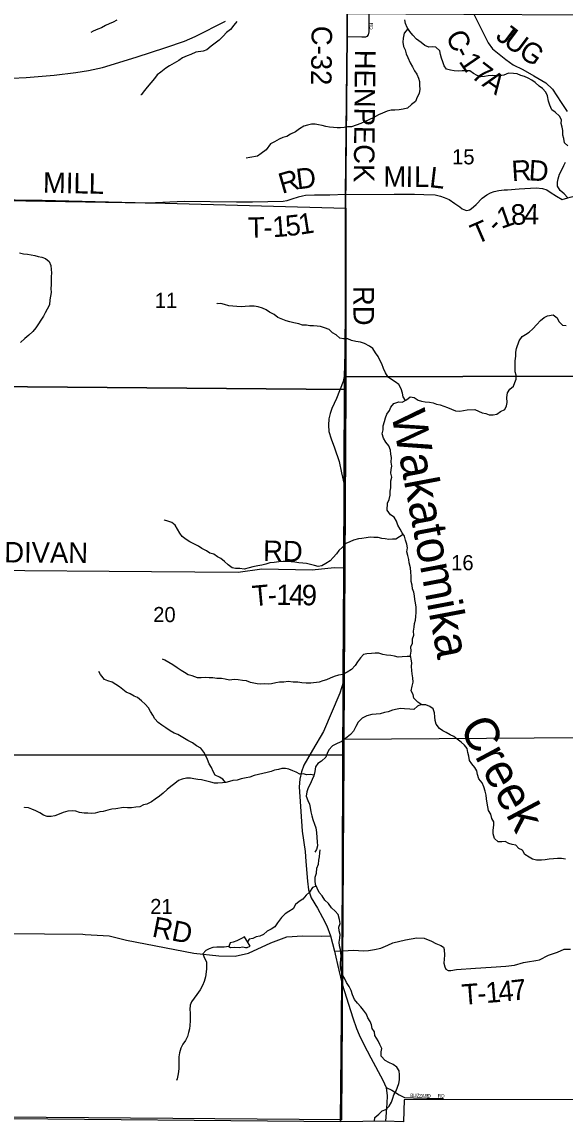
# Model space of a CAD drawing. Extents: x 1759416 to 2214760, y 252598 to 1116833.
# Drawn here: x 2024050 to 2031996, y 815661 to 831751 of the extents above; entities that cross this region are included whole.
import ezdxf

# ---------------------------------------------------------------- set-up
doc = ezdxf.new("R2010")
doc.units = 0
for name, color, linetype in [('GM_X_Adjacent_County', 7, 'Continuous'), ('GM_X_County', 7, 'Continuous'), ('GM_X_County_Road', 7, 'Continuous'), ('GM_X_County_Road_Text', 7, 'Continuous'), ('GM_X_Minor_Lake', 7, 'Continuous'), ('GM_X_Minor_River', 7, 'Continuous'), ('GM_X_Minor_River_Text', 7, 'Continuous'), ('GM_X_Section', 7, 'Continuous'), ('GM_X_Section_Text', 7, 'Continuous'), ('GM_X_State_Route', 7, 'Continuous'), ('GM_X_Township', 7, 'Continuous'), ('GM_X_Township_Road', 7, 'Continuous'), ('GM_X_Township_Road_Text', 7, 'Continuous'), ('GM_X_Township_ROW', 7, 'Continuous'), ('GM_X_Township_Subdivision', 7, 'Continuous'), ('GM_X_Township_Subdivision_Text', 7, 'Continuous')]:
    doc.layers.add(name, color=color, linetype=linetype)

msp = doc.modelspace()

# ---------------------------------------------------------------- linework, layer by layer
at = {"layer": 'GM_X_Adjacent_County'}
msp.add_lwpolyline([(2032253, 815990), (2029643, 815984), (2029631, 815665), (2029362, 815671), (2028709, 815661), (2023356, 815714), (2021728, 815742), (2020383, 815765), (2017999, 815806), (2014117, 815901), (2012614, 815938), (2008904, 816114), (2007002, 816215), (2006296, 816251), (2001880, 816522), (2001221, 816534)], dxfattribs=at)
at = {"layer": 'GM_X_County'}
msp.add_lwpolyline([(2032253, 815990), (2029643, 815984), (2029631, 815665), (2029362, 815671), (2028709, 815661), (2023356, 815714), (2021728, 815742), (2020383, 815765), (2017999, 815806), (2014117, 815901), (2012614, 815938), (2008904, 816114), (2007002, 816215), (2006296, 816251), (2001880, 816522), (2001221, 816534)], dxfattribs=at)
at = {"layer": 'GM_X_County_Road'}
for points in [[(2028809, 831909), (2028807, 831533), (2028785, 829229), (2028783, 827584), (2028777, 826935), (2028774, 826712), (2028769, 826590), (2028751, 826495), (2028652, 826246), (2028583, 826099), (2028560, 826027), (2028542, 825946), (2028534, 825855), (2028542, 825763), (2028573, 825656), (2028624, 825522), (2028690, 825322), (2028724, 825155), (2028763, 824988), (2028758, 823761), (2028754, 822861), (2028752, 822299), (2028751, 822090), (2028703, 821935), (2028461, 821373), (2028303, 821102), (2028172, 820880), (2028142, 820782), (2028115, 820674), (2028108, 820562), (2028149, 819914), (2028194, 819620), (2028203, 819471), (2028227, 819183), (2028245, 819057), (2028283, 818942), (2028373, 818791), (2028446, 818651), (2028509, 818532), (2028563, 818382)], [(2030657, 831875), (2030872, 831447), (2030934, 831359), (2031130, 831202), (2031239, 831126), (2031378, 831057), (2031540, 830965), (2031717, 830859), (2031813, 830767), (2031940, 830576), (2032029, 830443)], [(2028563, 818382), (2028622, 818160), (2028644, 818070), (2028665, 817965), (2028729, 817695), (2028735, 817678)], [(2028735, 817678), (2028893, 817184), (2028944, 817028), (2028983, 816934), (2029046, 816805), (2029153, 816600), (2029329, 816275), (2029379, 816168), (2029395, 816045), (2029390, 815938), (2029381, 815802), (2029369, 815671)]]:
    msp.add_lwpolyline(points, dxfattribs=at)
at = {"layer": 'GM_X_Minor_Lake'}
for points in [[(2027306, 818369), (2027262, 818345), (2027196, 818311), (2027138, 818293), (2027096, 818284), (2027076, 818228), (2027100, 818212), (2027162, 818217), (2027228, 818215), (2027280, 818221), (2027322, 818215), (2027346, 818213), (2027390, 818231)], [(2027306, 818369), (2027262, 818345), (2027196, 818311), (2027138, 818293), (2027096, 818284), (2027076, 818228), (2027100, 818212), (2027162, 818217), (2027228, 818215), (2027280, 818221), (2027322, 818215), (2027346, 818213), (2027390, 818231)], [(2027390, 818231), (2027306, 818369)]]:
    msp.add_lwpolyline(points, dxfattribs=at)
at = {"layer": 'GM_X_Minor_River'}
for points in [[(2025436, 831777), (2025384, 831747), (2025324, 831725), (2025270, 831701), (2025214, 831668), (2025158, 831646), (2025092, 831616), (2025058, 831600)], [(2027195, 831758), (2027151, 831704), (2027103, 831642), (2027045, 831598), (2026995, 831544), (2026933, 831485), (2026879, 831441), (2026817, 831399), (2026755, 831345), (2026703, 831325), (2026595, 831309), (2026523, 831275), (2026467, 831256), (2026399, 831228), (2026347, 831190), (2026207, 831110), (2026153, 831074), (2026081, 831017), (2026030, 830977), (2025988, 830923), (2025884, 830799), (2025844, 830747), (2025796, 830686), (2025788, 830684)], [(2030176, 831276), (2030164, 831328), (2030105, 831382), (2030053, 831388), (2030001, 831384), (2029943, 831406), (2029891, 831452), (2029821, 831500), (2029769, 831558), (2029723, 831612), (2029685, 831670), (2029661, 831728), (2029651, 831783)], [(2029698, 831650), (2029643, 831590), (2029629, 831516), (2029621, 831456), (2029635, 831394), (2029655, 831343), (2029673, 831287), (2029697, 831233), (2029728, 831153), (2029762, 831095), (2029792, 831039), (2029826, 830989), (2029852, 830932), (2029866, 830880), (2029868, 830820), (2029872, 830768), (2029862, 830706), (2029834, 830652), (2029806, 830590), (2029752, 830545), (2029693, 830491), (2029628, 830475), (2029570, 830467), (2029504, 830461), (2029450, 830463), (2029392, 830445), (2029324, 830417), (2029266, 830392), (2029200, 830356), (2029126, 830322), (2029074, 830294), (2029008, 830268), (2028938, 830240), (2028872, 830220), (2028814, 830216), (2028764, 830210), (2028712, 830204), (2028660, 830201), (2028610, 830209), (2028552, 830215), (2028498, 830225), (2028442, 830239), (2028390, 830247), (2028340, 830257), (2028286, 830255), (2028230, 830243), (2028174, 830227), (2028112, 830187), (2028052, 830147), (2027978, 830111), (2027924, 830076), (2027866, 830060), (2027812, 830036), (2027746, 829998), (2027688, 829970), (2027622, 829882), (2027552, 829827), (2027496, 829791), (2027386, 829769), (2027332, 829759)], [(2032039, 829938), (2031989, 829984), (2031977, 830048), (2031965, 830098), (2031962, 830162), (2031956, 830214), (2031942, 830267), (2031944, 830319), (2031914, 830375), (2031854, 830431), (2031802, 830467), (2031772, 830535), (2031754, 830591), (2031738, 830669), (2031715, 830726), (2031669, 830778), (2031619, 830814), (2031561, 830866), (2031511, 830902), (2031455, 830928), (2031403, 830956), (2031351, 830970), (2031297, 830994), (2031243, 830998), (2031167, 831004), (2031103, 830974), (2031049, 830966), (2030985, 830966), (2030931, 830970), (2030873, 830963), (2030819, 830953), (2030763, 830949), (2030710, 830967), (2030658, 830999), (2030602, 831035), (2030544, 831039), (2030492, 831035), (2030434, 831031), (2030374, 831037), (2030320, 831045), (2030264, 831059), (2030230, 831111), (2030210, 831169), (2030190, 831224), (2030176, 831276)], [(2032032, 829182), (2031982, 829238), (2031926, 829286), (2031888, 829350), (2031888, 829408), (2031897, 829458), (2031917, 829524), (2031951, 829589), (2031977, 829651), (2032001, 829701)], [(2024014, 828377), (2024070, 828361), (2024132, 828353), (2024236, 828337), (2024288, 828323), (2024341, 828313), (2024393, 828291), (2024447, 828247), (2024471, 828188), (2024477, 828132), (2024481, 828080), (2024479, 828022), (2024475, 827960), (2024477, 827908), (2024473, 827852), (2024475, 827795), (2024469, 827739), (2024458, 827685), (2024452, 827615), (2024420, 827553), (2024390, 827498), (2024364, 827448), (2024326, 827392), (2024290, 827336), (2024254, 827278), (2024210, 827226), (2024152, 827169), (2024094, 827123), (2024026, 827065)], [(2029661, 826216), (2029629, 826270), (2029617, 826320), (2029597, 826384), (2029565, 826450), (2029510, 826488), (2029456, 826522), (2029406, 826558), (2029368, 826620), (2029338, 826685), (2029314, 826749), (2029288, 826805), (2029260, 826857), (2029224, 826913), (2029185, 826973), (2029133, 827009), (2029063, 827049), (2029005, 827067), (2028937, 827079), (2028873, 827093), (2028817, 827115), (2028755, 827119), (2028703, 827125), (2028645, 827173), (2028593, 827205), (2028543, 827251), (2028479, 827277), (2028420, 827295), (2028370, 827303), (2028316, 827309), (2028264, 827309), (2028212, 827317), (2028156, 827319), (2028100, 827335), (2028026, 827349), (2027970, 827363), (2027918, 827379), (2027844, 827409), (2027792, 827431), (2027738, 827471), (2027674, 827509), (2027624, 827539), (2027568, 827565), (2027507, 827587), (2027447, 827593), (2027381, 827595), (2027317, 827589), (2027259, 827583), (2027195, 827589), (2027133, 827593), (2027075, 827601), (2027013, 827617), (2026959, 827635), (2026909, 827631), (2026907, 827637)], [(2029437, 824828), (2029439, 824888), (2029445, 824938), (2029445, 825042), (2029461, 825094), (2029446, 825151), (2029450, 825203), (2029462, 825255), (2029450, 825313), (2029456, 825379), (2029448, 825431), (2029444, 825487), (2029420, 825554), (2029372, 825604), (2029342, 825662), (2029321, 825728), (2029335, 825784), (2029337, 825842), (2029353, 825908), (2029369, 825961), (2029387, 826013), (2029427, 826069), (2029449, 826119), (2029493, 826169), (2029563, 826195), (2029615, 826191), (2029675, 826224), (2029731, 826266), (2029789, 826260), (2029845, 826220), (2029897, 826206), (2029951, 826194), (2030011, 826188), (2030065, 826180), (2030115, 826162), (2030167, 826150), (2030221, 826130), (2030275, 826112), (2030336, 826088), (2030396, 826066), (2030456, 826058), (2030512, 826068), (2030562, 826078), (2030678, 826082), (2030728, 826058), (2030786, 826036), (2030836, 826024), (2030886, 826004), (2030944, 826004), (2030996, 826016), (2031052, 826054), (2031116, 826083), (2031142, 826135), (2031152, 826187), (2031144, 826261), (2031154, 826327), (2031190, 826379), (2031242, 826426), (2031260, 826476), (2031282, 826526), (2031279, 826586), (2031267, 826636), (2031269, 826694), (2031267, 826744), (2031265, 826795), (2031275, 826863), (2031277, 826921), (2031287, 826975), (2031325, 827089), (2031367, 827152), (2031419, 827180), (2031471, 827216), (2031527, 827264), (2031585, 827328), (2031636, 827384), (2031690, 827431), (2031742, 827451), (2031824, 827469), (2031881, 827425), (2031907, 827371), (2031957, 827315), (2032011, 827313)], [(2031372, 819637), (2031318, 819661), (2031274, 819712), (2031224, 819718), (2031174, 819734), (2031122, 819762), (2031070, 819757), (2031018, 819761), (2030962, 819810), (2030943, 819878), (2030947, 819928), (2030953, 820002), (2030955, 820052), (2030927, 820102), (2030909, 820162), (2030877, 820215), (2030867, 820273), (2030857, 820323), (2030845, 820389), (2030840, 820441), (2030830, 820501), (2030810, 820563), (2030784, 820620), (2030736, 820682), (2030714, 820746), (2030706, 820798), (2030676, 820848), (2030632, 820900), (2030598, 820950), (2030589, 821012), (2030573, 821065), (2030563, 821123), (2030525, 821175), (2030475, 821217), (2030419, 821263), (2030369, 821301), (2030317, 821323), (2030259, 821357), (2030209, 821381), (2030159, 821415), (2030112, 821481), (2030094, 821533), (2030092, 821588), (2030086, 821648), (2030066, 821706), (2030016, 821740), (2029958, 821762), (2029902, 821762), (2029844, 821804), (2029786, 821862), (2029772, 821916), (2029745, 821970), (2029759, 822034), (2029773, 822095), (2029771, 822159), (2029761, 822217), (2029755, 822267), (2029749, 822325), (2029753, 822377), (2029747, 822429), (2029737, 822488), (2029745, 822548), (2029740, 822610), (2029762, 822666), (2029764, 822728), (2029782, 822784), (2029780, 822839), (2029788, 822901), (2029796, 822951), (2029808, 823001), (2029812, 823055), (2029820, 823113), (2029816, 823192), (2029808, 823254), (2029799, 823304), (2029795, 823356), (2029785, 823410), (2029765, 823460), (2029759, 823514), (2029745, 823567), (2029743, 823645), (2029741, 823705), (2029733, 823765), (2029717, 823839), (2029710, 823891), (2029696, 823948), (2029682, 824000), (2029692, 824062), (2029680, 824114), (2029664, 824170), (2029646, 824228), (2029612, 824280), (2029586, 824334), (2029552, 824391), (2029530, 824451), (2029495, 824509), (2029443, 824543), (2029395, 824609), (2029399, 824711), (2029423, 824767), (2029437, 824828)], [(2029627, 824256), (2029572, 824220), (2029520, 824184), (2029470, 824186), (2029416, 824180), (2029366, 824190), (2029314, 824196), (2029264, 824210), (2029200, 824212), (2029146, 824216), (2029088, 824208), (2029022, 824198), (2028972, 824189), (2028900, 824171), (2028848, 824149), (2028790, 824121), (2028740, 824069), (2028688, 824023), (2028654, 823971), (2028602, 823920), (2028558, 823868), (2028494, 823828), (2028440, 823794), (2028386, 823788), (2028328, 823802), (2028274, 823818), (2028212, 823828), (2028160, 823836), (2028102, 823842), (2028045, 823850), (2027991, 823856), (2027931, 823862), (2027871, 823862), (2027809, 823856), (2027739, 823847), (2027679, 823839), (2027617, 823821), (2027559, 823805), (2027499, 823795), (2027427, 823781), (2027373, 823769), (2027299, 823749), (2027239, 823759), (2027175, 823757), (2027125, 823767), (2027067, 823813), (2027013, 823861), (2026959, 823905), (2026909, 823927), (2026857, 823965), (2026800, 823983), (2026748, 824017), (2026684, 824051), (2026634, 824083), (2026564, 824117), (2026504, 824147), (2026454, 824183), (2026396, 824225), (2026360, 824275), (2026328, 824332), (2026292, 824390), (2026241, 824432), (2026185, 824450), (2026135, 824464), (2026131, 824468)], [(2029740, 822471), (2029687, 822468), (2029615, 822467), (2029553, 822461), (2029499, 822473), (2029446, 822487), (2029386, 822491), (2029330, 822501), (2029270, 822519), (2029216, 822517), (2029164, 822513), (2029096, 822511), (2029046, 822499), (2029002, 822449), (2028960, 822391), (2028924, 822338), (2028872, 822282), (2028806, 822240), (2028744, 822208), (2028682, 822198), (2028620, 822176), (2028562, 822154), (2028506, 822130), (2028454, 822113), (2028398, 822097), (2028278, 822081), (2028206, 822079), (2028144, 822083), (2028086, 822095), (2028020, 822095), (2027944, 822105), (2027884, 822093), (2027820, 822093), (2027766, 822085), (2027702, 822071), (2027652, 822065), (2027598, 822069), (2027546, 822065), (2027492, 822070), (2027442, 822078), (2027392, 822092), (2027334, 822112), (2027276, 822118), (2027212, 822130), (2027154, 822134), (2027086, 822126), (2027021, 822138), (2026969, 822150), (2026903, 822150), (2026843, 822158), (2026789, 822158), (2026737, 822162), (2026671, 822160), (2026617, 822160), (2026539, 822186), (2026483, 822202), (2026429, 822236), (2026377, 822266), (2026319, 822302), (2026257, 822348), (2026199, 822382), (2026142, 822416), (2026108, 822432)], [(2027030, 820628), (2026990, 820678), (2026938, 820704), (2026879, 820732), (2026849, 820788), (2026823, 820845), (2026787, 820901), (2026763, 820963), (2026741, 821017), (2026713, 821069), (2026665, 821127), (2026603, 821165), (2026545, 821207), (2026478, 821243), (2026426, 821269), (2026332, 821329), (2026278, 821349), (2026216, 821382), (2026154, 821428), (2026096, 821466), (2026044, 821504), (2025996, 821558), (2025966, 821610), (2025931, 821668), (2025899, 821718), (2025853, 821772), (2025801, 821822), (2025741, 821872), (2025691, 821888), (2025633, 821922), (2025575, 821950), (2025525, 821987), (2025475, 822025), (2025425, 822061), (2025369, 822093), (2025308, 822115), (2025258, 822135), (2025200, 822207), (2025174, 822253)], [(2029893, 821768), (2029838, 821746), (2029782, 821696), (2029724, 821699), (2029646, 821707), (2029590, 821711), (2029538, 821701), (2029472, 821683), (2029408, 821663), (2029356, 821651), (2029290, 821629), (2029232, 821625), (2029168, 821621), (2029096, 821603), (2029026, 821566), (2028970, 821510), (2028936, 821448), (2028902, 821380), (2028858, 821330), (2028786, 821273), (2028728, 821225), (2028660, 821199), (2028596, 821161), (2028540, 821105), (2028518, 821053), (2028494, 820996), (2028434, 820940), (2028378, 820906), (2028344, 820854), (2028334, 820786), (2028320, 820726), (2028296, 820671), (2028265, 820603), (2028237, 820549), (2028219, 820489), (2028209, 820429), (2028235, 820363), (2028259, 820312), (2028265, 820260), (2028275, 820200), (2028291, 820140), (2028307, 820086), (2028328, 820016), (2028348, 819962), (2028360, 819895), (2028364, 819823), (2028368, 819757), (2028376, 819699), (2028362, 819645), (2028334, 819607)], [(2028322, 820734), (2028270, 820744), (2028218, 820738), (2028164, 820754), (2028114, 820750), (2028064, 820780), (2028012, 820796), (2027954, 820822), (2027904, 820830), (2027854, 820833), (2027804, 820819), (2027746, 820807), (2027694, 820787), (2027640, 820775), (2027576, 820759), (2027510, 820745), (2027448, 820727), (2027382, 820703), (2027330, 820693), (2027256, 820679), (2027198, 820660), (2027136, 820656), (2027086, 820640), (2027032, 820628), (2026982, 820620), (2026918, 820618), (2026868, 820618), (2026812, 820632), (2026736, 820650), (2026675, 820664), (2026625, 820670), (2026567, 820680), (2026515, 820688), (2026457, 820688), (2026393, 820678), (2026339, 820658), (2026285, 820614), (2026227, 820567), (2026173, 820527), (2026117, 820473), (2026061, 820427), (2025997, 820381), (2025944, 820344), (2025878, 820310), (2025828, 820300), (2025776, 820272), (2025717, 820264), (2025651, 820256), (2025593, 820256), (2025535, 820262), (2025421, 820240), (2025365, 820236), (2025305, 820220), (2025239, 820204), (2025187, 820199), (2025123, 820179), (2025071, 820173), (2025015, 820177), (2024959, 820179), (2024893, 820189), (2024837, 820209), (2024785, 820211), (2024723, 820209), (2024653, 820189), (2024595, 820163), (2024531, 820139), (2024479, 820131), (2024419, 820129), (2024363, 820149), (2024309, 820181), (2024253, 820213), (2024195, 820235), (2024143, 820255), (2024089, 820263), (2024085, 820267)], [(2029206, 815675), (2029215, 815726), (2029271, 815776), (2029321, 815824), (2029373, 815844), (2029425, 815894), (2029455, 815950), (2029477, 816008), (2029493, 816060), (2029527, 816116), (2029543, 816170), (2029563, 816226), (2029573, 816280), (2029576, 816350), (2029570, 816408), (2029536, 816462), (2029482, 816504), (2029418, 816530), (2029364, 816561), (2029308, 816625), (2029306, 816685), (2029316, 816735), (2029286, 816797), (2029261, 816849), (2029213, 816927), (2029207, 816979), (2029173, 817029), (2029163, 817080), (2029143, 817130), (2029111, 817186), (2029089, 817240), (2029049, 817296), (2029010, 817348), (2028962, 817400), (2028918, 817452), (2028888, 817521), (2028868, 817583), (2028838, 817643), (2028798, 817701), (2028776, 817755), (2028739, 817813), (2028719, 817879), (2028713, 817933), (2028709, 817985), (2028715, 818039), (2028723, 818091), (2028711, 818182), (2028697, 818236), (2028693, 818290), (2028701, 818350), (2028704, 818402), (2028690, 818456), (2028688, 818510), (2028704, 818566), (2028698, 818622), (2028678, 818694), (2028634, 818746), (2028580, 818792), (2028534, 818855), (2028483, 818907), (2028441, 818969), (2028401, 819019), (2028371, 819081), (2028345, 819135), (2028339, 819189), (2028341, 819243), (2028359, 819303), (2028365, 819375), (2028388, 819433), (2028392, 819491), (2028402, 819542), (2028408, 819598), (2028414, 819640)], [(2032002, 819505), (2031946, 819515), (2031886, 819513), (2031828, 819511), (2031766, 819507), (2031704, 819497), (2031650, 819490), (2031580, 819490), (2031522, 819508), (2031470, 819534), (2031410, 819576), (2031380, 819628), (2031360, 819648)], [(2028355, 819113), (2028303, 819089), (2028259, 819021), (2028207, 818977), (2028159, 818922), (2028105, 818884), (2028053, 818842), (2028019, 818780), (2027953, 818738), (2027903, 818706), (2027846, 818652), (2027790, 818574), (2027750, 818518), (2027694, 818484), (2027638, 818452), (2027586, 818406), (2027532, 818379), (2027478, 818369), (2027428, 818347), (2027376, 818333), (2027349, 818298)], [(2027079, 818226), (2027010, 818218), (2026902, 818218), (2026844, 818212), (2026790, 818192), (2026738, 818172), (2026694, 818120), (2026720, 818056), (2026748, 818004), (2026752, 817896), (2026736, 817784), (2026717, 817714), (2026691, 817658), (2026655, 817592), (2026609, 817524), (2026569, 817472), (2026529, 817418), (2026513, 817368), (2026507, 817308), (2026509, 817256), (2026513, 817194), (2026513, 817140), (2026508, 817074), (2026502, 817024), (2026488, 816970), (2026470, 816914), (2026442, 816852), (2026404, 816800), (2026376, 816742), (2026356, 816672), (2026346, 816612), (2026344, 816560), (2026346, 816506), (2026346, 816448), (2026341, 816396), (2026331, 816342), (2026321, 816292), (2026313, 816266)]]:
    msp.add_lwpolyline(points, dxfattribs=at)
at = {"layer": 'GM_X_Section'}
for points in [[(2028813, 831877), (2032216, 831858), (2032212, 826573), (2028790, 826560), (2028791, 829028), (2028813, 831580)], [(2026144, 829099), (2028791, 829028), (2028790, 826560), (2028791, 826378), (2023545, 826419), (2023515, 829145)], [(2032212, 826573), (2032243, 821279), (2028758, 821254), (2028791, 826378), (2028790, 826560)], [(2023545, 826419), (2028791, 826378), (2028758, 821254), (2028758, 821030), (2023486, 821025)], [(2028758, 821030), (2028725, 815691), (2024403, 815725), (2023391, 815733), (2023486, 821025)]]:
    msp.add_lwpolyline(points, close=True, dxfattribs=at)
at = {"layer": 'GM_X_State_Route'}
msp.add_lwpolyline([(2023902, 830930), (2024112, 830941), (2024521, 830974), (2024839, 831012), (2025024, 831043), (2025228, 831086), (2025719, 831239), (2026154, 831378), (2026426, 831471), (2026582, 831537), (2027027, 831764)], dxfattribs=at)
at = {"layer": 'GM_X_Township'}
for points in [[(2028809, 831909), (2028807, 831533), (2028785, 829229), (2028783, 827584), (2028777, 826935), (2028774, 826712), (2028769, 826590), (2028763, 824988), (2028758, 823761), (2028754, 822861), (2028752, 822299), (2028751, 822090), (2028734, 818183), (2028729, 817695), (2028709, 815661), (2023356, 815714), (2021728, 815742), (2020383, 815765), (2017999, 815806), (2014117, 815901)], [(2032253, 815990), (2029643, 815984), (2029631, 815665), (2029362, 815671), (2028709, 815661), (2028729, 817695), (2028734, 818183), (2028751, 822090), (2028752, 822299), (2028754, 822861), (2028758, 823761), (2028763, 824988), (2028769, 826590), (2028774, 826712), (2028777, 826935), (2028783, 827584), (2028785, 829229), (2028807, 831533), (2028809, 831909)]]:
    msp.add_lwpolyline(points, dxfattribs=at)
at = {"layer": 'GM_X_Township_Road'}
for points in [[(2028785, 829229), (2029497, 829232), (2029793, 829234), (2029929, 829226), (2030096, 829222), (2030176, 829205), (2030230, 829185), (2030300, 829154), (2030385, 829098), (2030458, 829047), (2030492, 829017), (2030538, 828997), (2030559, 828996), (2030599, 829002), (2030624, 829020), (2030697, 829084), (2030785, 829172), (2030854, 829224), (2030907, 829254), (2030957, 829272), (2031027, 829286), (2031106, 829294), (2031154, 829298), (2031324, 829309), (2031575, 829327), (2031667, 829315), (2031729, 829294), (2031779, 829263), (2031873, 829205)], [(2028785, 829229), (2028553, 829220), (2028332, 829220), (2028201, 829214), (2028157, 829206), (2028092, 829189), (2027998, 829158), (2027927, 829137), (2027873, 829124), (2027424, 829115), (2027190, 829115), (2026422, 829124), (2025902, 829103), (2024344, 829140), (2023553, 829150)], [(2028758, 823761), (2028619, 823768), (2028297, 823735), (2027561, 823749), (2027214, 823699), (2025944, 823710), (2023465, 823728)], [(2023253, 818421), (2024939, 818407), (2024976, 818402), (2025328, 818386), (2025577, 818323), (2026566, 818132), (2026929, 818090), (2027170, 818086), (2027364, 818132), (2027689, 818284), (2027926, 818369), (2028154, 818386), (2028435, 818381), (2028563, 818382)], [(2028727, 818166), (2028734, 818166), (2028825, 818169), (2028907, 818173), (2028975, 818169), (2029048, 818166), (2029119, 818169), (2029207, 818184), (2029299, 818206), (2029402, 818247), (2029475, 818281), (2029663, 818324), (2029826, 818354), (2029933, 818351), (2030044, 818305), (2030105, 818271), (2030179, 818242), (2030216, 818217), (2030230, 818184), (2030232, 818101), (2030225, 817985), (2030237, 817932), (2030251, 817897), (2030288, 817879), (2030327, 817876), (2030408, 817890), (2030686, 817913), (2030916, 817927), (2031132, 817941), (2031259, 817957), (2031391, 817994), (2031447, 818006), (2031568, 818022), (2031623, 818034), (2031755, 818101), (2031887, 818147), (2031985, 818187), (2032075, 818189)], [(2028622, 818160), (2028727, 818166)]]:
    msp.add_lwpolyline(points, dxfattribs=at)
at = {"layer": 'GM_X_Township_ROW'}
msp.add_lwpolyline([(2031873, 829205), (2031952, 829156), (2032037, 829178), (2032073, 829190), (2032209, 829222)], dxfattribs=at)
at = {"layer": 'GM_X_Township_Subdivision'}
for points in [[(2029142, 832533), (2029142, 832522), (2029145, 832214), (2029151, 832156), (2029138, 832066), (2029126, 831911), (2029125, 831607), (2029118, 831565), (2029097, 831539), (2029078, 831530), (2029024, 831530), (2028807, 831533)], [(2029379, 816168), (2029462, 816125), (2029571, 816059), (2029646, 816018), (2029777, 816015), (2029974, 816008), (2030220, 816007)]]:
    msp.add_lwpolyline(points, dxfattribs=at)

# ---------------------------------------------------------------- texts
at = {"layer": 'GM_X_County_Road_Text'}
for s, rotation, p in [('C-32', 269.3077, (2028289, 831697)), ('C', 296.3766, (2030243, 831545)), ('J', 323.3022, (2030966, 831514)), ('U', 323.3238, (2031079, 831429)), ('G', 325.3084, (2031300, 831265)), ('HENPECK', 269.4035, (2028924, 831347)), ('1', 304.3899, (2030433, 831175)), ('-', 297.5414, (2030356, 831318)), ('7', 322.4084, (2030608, 830948)), ('A', 325.5173, (2030769, 830825)), ('RD', 270, (2028901, 827890))]:
    msp.add_text(s, height=300, rotation=rotation, dxfattribs=at).set_placement(p)
at = {"layer": 'GM_X_Minor_River_Text'}
for s, rotation, p in [('Wakatomika', 280.7167, (2029450, 826029)), ('Creek', 298.0591, (2030443, 821439))]:
    msp.add_text(s, height=500, rotation=rotation, dxfattribs=at).set_placement(p)
at = {"layer": 'GM_X_Section_Text'}
for s, p in [('15', (2030343, 829669)), ('11', (2025992, 827569)), ('16', (2030330, 823732)), ('20', (2025970, 822973)), ('21', (2025926, 818703))]:
    msp.add_text(s, height=221, rotation=0, dxfattribs=at).set_placement(p)
at = {"layer": 'GM_X_Township_Road_Text'}
for s, rotation, p in [('D', 6.984, (2028080, 829302)), ('M', 359.6382, (2029337, 829342)), ('I', 359.637, (2029663, 829340)), ('L', 359.4236, (2029786, 829339)), ('L', 353.2301, (2030002, 829337)), ('R', 3.5208, (2031222, 829421)), ('D', 356.4096, (2031458, 829436)), ('MILL', 358.8768, (2024355, 829254)), ('R', 16.2888, (2027856, 829236)), ('1', 19.2751, (2031062, 828722)), ('8', 4.5739, (2031216, 828778)), ('4', 359.1569, (2031393, 828793)), ('T', 1.095, (2027359, 828593)), ('1', 4.3124, (2027725, 828602)), ('5', 6.3193, (2027921, 828617)), ('1', 8.8221, (2028119, 828639)), ('T', 23.4223, (2030697, 828493)), ('-', 45.4008, (2031005, 828653)), ('-', 2.0761, (2027589, 828597)), ('DIVAN', 359.5727, (2023790, 823846)), ('RD', 359.0118, (2027576, 823868)), ('T', 5.3068, (2027432, 823204)), ('1', 359.0815, (2027770, 823225)), ('4', 359.0164, (2027954, 823222)), ('9', 359.8324, (2028144, 823219)), ('-', 0.3942, (2027648, 823224)), ('RD', 349.0774, (2025941, 818375)), ('1', 4.61, (2030845, 817401)), ('4', 5.1048, (2031032, 817416)), ('7', 6.5922, (2031225, 817434)), ('T', 4.4508, (2030498, 817374)), ('-', 4.4859, (2030722, 817391))]:
    msp.add_text(s, height=300, rotation=rotation, dxfattribs=at).set_placement(p)
at = {"layer": 'GM_X_Township_Subdivision_Text'}
for s, rotation, p in [('RD', 270, (2029136, 831740)), ('B', 358.0083, (2029730, 816028)), ('L', 358.0078, (2029769, 816026)), ('I', 358.0108, (2029805, 816025)), ('Z', 358.0078, (2029827, 816024)), ('Z', 358.0189, (2029862, 816023)), ('A', 358.0108, (2029897, 816022)), ('R', 358.2061, (2029941, 816020)), ('D', 359.717, (2029982, 816019)), ('RD', 0, (2030134, 816019))]:
    msp.add_text(s, height=50, rotation=rotation, dxfattribs=at).set_placement(p)

doc.saveas('drawing.dxf')
